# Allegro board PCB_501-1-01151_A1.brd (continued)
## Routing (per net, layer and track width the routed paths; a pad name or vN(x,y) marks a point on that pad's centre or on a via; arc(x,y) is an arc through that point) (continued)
VDD_PERI_3V3: length 139.9
  TOP w0.142: Q6.2 82.24,6.58 82.32,6.65 R261.1
  TOP w0.203: 29.21,41.15 29.21,41.14 U3.A1 ; U8.J10 77.97,25.64 v1(77.47,25.15) ; C38.1 v1(28.32,40.01) ; C38.1 v1(27.57,40) ; C38.1 v1(27.45,40.75) ; U8.F5 76.84,23.76 v1(76.84,24) 76.39,24 76.27,23.89 U8.E6 ; 29.08,40.26 U3.B1 U3.A1 ; U3.A1 29.23,40.76 29.08,40.62 29.08,40.39 ; U8.K9 78.98,25.91 v1(78.98,25.91)
  TOP w0.381: v1(36.98,26.45) 36.98,26.09 R812.2 ; R176.1 v1(22.46,39.75) ; R785.2 48.9,18.41 ; R177.1 v1(8.27,47.14) ; R267.2 R854.2 13.46,56.77 14.48,55.75 14.48,55.69 v1(14.53,55.64) ; v1(51.05,16.79) 50.97,16.87 C120.1 ; R264.1 v1(2.39,49.8) ; v1(12.7,51.04) 12.7,51.05 12.85,51.2 R857.2 R855.2 ; FB9.1 57.51,4.57 57.28,4.33 v1(57.28,3.58) ; v1(16.26,71.63) 14.85,70.22 D29.2 ; v1(37.34,15.75) 37.02,15.43 R811.2 36.57,16.04 36.6,16.06 R810.2 ; R813.2 36.94,27.88 v1(37.11,28.05) ; FB6.1 69.72,4.22 v1(69.31,3.8) ; v1(15.49,72.39) 15.11,72.01 R265.2 ; v1(20.55,49.66) C585.1 C586.1 H4.5 ; R116.1 v1(15.24,36.85) ; C190.1 64.33,17.04 64.41,17.12 v1(64.62,17.12) ; R262.1 v1(84.84,5.97) ; C597.1 v1(80.54,58.29) ; C597.1 v1(80.54,56.79) ; C597.1 v1(81.28,57.53) ; v1(42.04,18.8) FB1.1 v1(42.78,19.54) ; C114.1 94.6,19.85 C115.1 94.33,18.41 v1(93.5,19.24) ; v1(33.15,10.03) R109.1 R110.2 ; R261.1 82.92,7.37 82.94,7.35 C198.1 v1(84.56,7.35) ; R120.2 v1(21.61,36.85) ; R128.2 R124.1 v1(32.89,35.81) ; R113.2 v1(44.07,20.07)
  TOP w0.508: 52.04,16.76 C117.1 ; C117.1 53.18,16.76 ; C117.1 52.61,16.19
  L4_SIG2 w0.381: v1(28.96,47.63) 31.12,47.63 31.86,48.37 v1(31.86,50.27)
  BOTTOM w0.203: U10.78 51.21,16.95 v1(51.05,16.79)
  BOTTOM w0.254: C118.1 44.83,12.59 44.83,12.95 45.22,13.34 U10.11 ; U13.8 84.19,63.23 84.46,63.5 84.46,63.57 84.47,63.59 C128.1 v1(84.47,65.13) ; U10.51 45.72,28.27 45.59,28.39 C121.1 ; U10.65 53.2,23.45 53.3,23.35 C119.1
  BOTTOM w0.305: U20.3 18.84,46.04 v1(19.87,47.06) ; U23.4 32.17,70.57 31.98,70.76 C181.1
  BOTTOM w0.356: v1(8.13,44.7) 8.36,44.94 C170.1 C171.1 10.33,44.77 U20.12
  BOTTOM w0.381: R131.1 v1(16.62,12.34) ; R863.1 v1(40.51,9.62) ; R847.2 v1(38.33,33.29) ; R571.1 v1(50.16,10.54) ; R114.2 50.06,9.51 v1(50.15,9.42) ; v1(78.98,25.91) 79.1,25.8 C104.1 ; R180.2 R168.1 v1(11.28,41.89) ; C181.1 v1(31.12,71.5) 31.1,71.52 R185.2 ; v1(93.6,20.03) 93.85,19.77 94.15,19.77 ; v1(20.83,41.4) 20.96,41.27 C172.1 ; v1(10.68,38.83) 10.27,39.24 C173.1 ; U24.7 61.95,17.5 v1(62.23,17.78) ; v1(58.34,14) 58.67,14 C188.1 59.06,13.6 U24.1 ; v1(32.77,67.94) 33.01,67.7 U23.16 ; U22.16 v1(28.96,47.63) ; FB19.1 5.95,28.22 6.06,28.33 6.06,29.43 7.62,30.99 7.88,30.99 7.9,31.01 FB20.1 9.12,31.62 v1(9.65,31.62) ; J2.4 94.15,19.77 ; 94.15,19.77 93.84,19.46 93.72,19.46 v1(93.5,19.24) ; R845.2 38.1,10.11 v1(37.84,9.85) ; R799.2 v1(44.7,30.99) ; v1(18.03,51.1) 18.54,50.59 18.54,49.15 18.14,48.75 R167.2 ; C103.1 77.24,23.6 v1(76.84,24) ; FB18.1 v1(19.58,23.13) ; v1(85.86,95.89) D9.2 v1(86.74,95.12) ; R846.1 R864.1 41.27,33.81 v1(41.4,33.94) ; v1(54.1,13.08) 54.38,12.81 R130.2 ; R798.2 44.94,10.27 v1(45.13,10.08) ; R844.1 39.37,10.41 v1(39.62,10.16) ; R783.2 v1(53.59,10.54) ; C118.1 v1(44.81,11.83) ; R387.2 33.06,40.51 32.64,40.09 v1(32.64,39.37) ; v1(31.86,50.27) C180.1 31.86,48.92 31.84,48.9 U22.4 ; v1(64.62,17.12) 65.05,17.55 66.48,17.55 U24.10 ; R77.1 v1(79.88,18.13) ; v1(58.62,16.79) C607.1 58.35,16.05 58.22,15.91 Y1.4 ; C119.1 v1(53.85,22.61) ; R115.2 v1(50.93,32.38) ; C105.1 77.11,25.51 v1(77.47,25.15) ; FB17.1 v1(26.82,18.31) ; R134.1 v1(20.68,12.34) ; R784.2 v1(54.5,26.31) ; C121.1 v1(44.72,29.06)
  vias: v1(28.32,39.24) v1(33.58,31.56) v1(34.22,31.58) v1(34.89,31.59) v1(53.47,14.1) v1(54.23,14.1) v1(81.91,60.96) v1(82.04,59.18) v1(82.04,57.66)
VDD_PERI_FIL_3V3: length 29.1
  TOP w0.254: v1(75.82,73.66) 75.82,73.41 75.5,73.09 U14.64 ; v1(75.98,67.07) 75.81,67.07 75.78,67.09 U14.52 ; v1(72.52,74.55) 72.49,74.52 U14.5 ; v1(75.95,69.59) U14.57 ; U14.24 65.55,69.59 65.52,69.62 v1(65.52,69.62) ; U14.10 69.99,74.43 v1(70.1,74.55) ; U14.46 v1(73.49,64.18)
  TOP w0.381: R162.1 v1(80.42,64.39) ; R816.2 v1(64.9,62.74) ; R163.1 80.58,67.82 v1(80.81,67.59) ; R817.2 v1(61.72,67.47) ; R140.1 v1(72.64,58.01) ; R820.2 68.33,61.72 v1(68.07,61.47) ; R161.1 v1(80.42,65.53) ; R819.2 v1(60.8,72.77) ; R818.2 v1(60.93,70.49) ; R142.1 v1(70.1,58.01) ; R141.1 v1(73.79,58.01) ; R165.1 v1(80.42,66.68)
  BOTTOM w0.254: C142.1 v1(72.52,74.55) ; C139.1 v1(70.1,74.55)
  BOTTOM w0.305: C140.1 75.81,69.72 v1(75.95,69.59)
  BOTTOM w0.381: 66.04,72.14 66.27,71.9 C131.1 C133.1 66,70.1 v1(65.52,69.62) ; C143.1 C141.1 75.96,67.06 v1(75.98,67.07) ; v1(73.49,64.18) 73.53,64.22 C137.1 ; R143.1 67.33,76.09 ; C138.1 v1(75.82,73.66)
  BOTTOM w0.508: 68.33,76.66 R143.1 68.9,76.09 ; 74.11,64.88 C137.1 72.96,64.88 ; 70.68,73.81 C139.1 69.53,73.81 ; 75.33,68.77 C143.1 75.9,68.2
  vias: v1(75.73,59.47) v1(75.83,60.45) v1(76.84,60.45)
VDD_PMIC_LS_5V0: length 29
  TOP w0.178: R187.1 31.99,58.54 32.72,59.26 32.72,65.11 32.51,65.32 v1(32.51,65.79)
  TOP w0.203: U6.T12 57.51,47.67 57.51,47.9 U6.U12
  TOP w0.254: R187.1 31.99,56.38 v1(31.62,56.01) ; U6.U12 57.38,48.6
  TOP w0.508: 59.54,58.14 59.54,56.44 58.69,55.6 58.55,55.6 56.93,53.99 56.93,52.92 57.55,52.3 C94.1 C95.1 57.55,49.49 57.47,49.41 57.47,48.68 57.38,48.6
  BOTTOM w0.178: v1(32.51,65.79) 33.05,65.25 34.02,65.25 35.25,66.48 U23.14
  BOTTOM w0.381: R36.1 29.44,88.12
  vias: v1(31.62,55.24) v1(32.38,56.01) v1(32.38,55.24) v1(55.07,51.71) v1(59.05,59.18) v1(59.56,58.55) v1(59.82,59.18) v1(88.39,57.4) v1(88.77,58.42) v1(88.94,57.68) v1(88.9,56.77)
VDD_PMIC_LS_5V0_SNS: length 16.7
  TOP w0.178: v1(33.27,65.79) 33.27,65.32 33.1,65.14 33.1,59.49 33.79,58.79 R187.2 ; U1.33 40.47,57.93 39.95,57.4 39.22,57.4
  TOP w0.381: R187.2 v1(34.92,57.28)
  BOTTOM w0.178: U23.15 34.6,66.68 34.34,66.42 33.71,66.42 33.12,67.01 32.87,67.01 32.69,66.83 32.69,66.37 v1(33.27,65.79)
  vias: v1(35.69,57.28) v1(50.8,58.17) v1(51.44,58.17)
VDD_SNVS_CAP: length 13.7
  TOP w0.203: U6.N12 v1(57.38,45.4)
  L4_SIG2 w0.142: v1(57.38,45.4) 57.79,45.8 57.79,48.22 56.1,49.91 52.45,49.91 52.24,50.12 51.51,50.12 51.3,49.91 v1(51.05,49.91)
  BOTTOM w0.142: TP54.1 49.78,49.75 49.94,49.91 v1(51.05,49.91)
  BOTTOM w0.381: v1(57.38,45.4) 57.4,45.38 C62.1
VDD_SNVS_IN: length 92.5
  TOP w0.203: U6.P12 v1(57.38,46.2)
  TOP w0.381: v1(57.02,62.23) 56.85,62.06 U2.5 v1(57.79,61.36) ; v1(52.83,69.09) 52.83,68.73 R27.1 ; v1(37.19,66.68) R802.1 v1(36.54,67.69) ; v1(41.15,47.62) 41.29,47.48 R26.1 ; v1(55.92,67.94) 56.5,67.94 57.02,67.42 R23.1 ; R18.2 v1(55.63,64.87)
  TOP w0.508: v1(35.69,43.81) 35.94,44.07 35.94,45.08 D6.1 34.67,45.21 34.16,44.7 v1(34.16,43.43) ; TP36.1 36.7,68.45
  L4_SIG2 w0.381: v1(92.18,58.8) 90.4,60.58 83.48,60.58 82.51,61.56 74.26,61.56 73.53,60.83 66.68,60.83 65.95,61.56 63.79,61.56 62.48,62.87 58.55,62.87 57.79,62.1 v1(57.79,61.36)
  BOTTOM w0.142: v1(57.38,46.2) 57.62,46.2 58.02,46.6 60.06,46.6 60.2,46.74 60.2,47.49 60.61,47.9 C61.1
  BOTTOM w0.508: R32.2 16.91,76.71 v1(15.75,76.71) ; v1(92.18,58.8) 92.18,56.58 95.52,53.23 R576.1 R575.1 ; R763.2 37.97,65.89 v1(37.19,66.68)
  vias: v1(19.68,68.96) v1(20.7,68.96) v1(20.7,67.94) v1(35.14,43.43) v1(35.94,66.77)
VDD_SOC_ARM_IN: length 57.9
  TOP w0.142: U1.47 45.87,55.35 46.92,54.3 46.92,53.67 46.93,53.66 46.93,53.32 46.92,53.31 46.92,49.98 46.86,49.93 v1(46.86,49.53)
  TOP w0.254: U6.K10 v1(58.98,43) ; U6.J9 v1(60.61,41.37) ; U6.H9 v1(60.61,40.57) ; U6.H10 v1(58.98,40.57) ; U6.J10 v1(58.98,41.37) ; U6.K9 v1(60.61,43)
  BOTTOM w0.142: 60.96,43.43 61.01,43.48 61.01,45.18 60.99,45.2 60.99,45.65 60.84,45.8 56.42,45.8 56.19,46.03 56.19,46.36 55.95,46.6 55.38,46.6 54.58,47.4 52.55,47.4 52.32,47.62 50.04,47.62 48.76,48.9 47.15,48.9 47.09,48.96 47.09,48.97 46.86,49.19 v1(46.86,49.53) ; U22.11 30.54,43.1 31.1,42.55 45.34,42.55 45.88,43.09 45.88,47.13 47.35,48.61 48.64,48.61 48.99,48.26 48.99,47.28 49.28,46.99 v1(50.16,46.99)
  BOTTOM w0.381: v1(58.98,43) 59.66,43.67 C45.1 59.94,43.67 v1(60.61,43)
  vias: v1(50.8,46.99) v1(50.81,46.24) v1(51.69,46.99) v1(51.69,46.23)
VDD_SOC_ARM_IN_SNS: length 27
  BOTTOM w0.142: v1(47.75,47.75) 47.75,47.5 48.01,47.24 48.5,47.24 48.64,47.39 48.64,48.12 48.5,48.26 47.5,48.26 46.23,46.99 46.23,42.95 45.48,42.2 30.95,42.2 29.89,43.27 U22.12
VDD_SOC_CAP: length 23.1
  TOP w0.203: U6.J11 v1(58.18,41.37) ; U6.H8 v1(61.41,40.57) ; U6.L11 58.2,43.78 v1(58.16,43.78) ; U6.K11 v1(59.01,42.17) ; U6.L9 v1(60.61,43.8) ; U6.L8 v1(61.41,43.8) ; U6.L10 v1(58.98,43.8) ; U6.G8 v1(61.41,39.77) ; U6.K8 v1(61.41,43)
  TOP w0.254: U6.H8 61.09,41.07 61.09,41.69 U6.J8 U6.K8
  BOTTOM w0.142: 66.42,44.42 65.8,44.42 65.58,44.2 65.25,44.2 65.01,44.43 65.01,44.84 64.86,45 61.7,45
  BOTTOM w0.203: 61.7,45 61.41,44.71 v1(61.41,43.8)
  BOTTOM w0.381: v1(61.41,43.8) v1(61.41,43) 61.32,42.91 C51.1 61.32,40.98 61.34,40.97 C52.1 61.34,40.9 61.34,40.89 61.34,40.73 61.41,40.66 v1(61.41,40.57) v1(61.41,39.77) ; 66.42,44.42 66.9,44.42 67.06,44.58 67.06,45.22 67.91,46.08 ; TP50.1 68.07,45.09 67.91,45.25 67.91,46.08 ; 67.91,46.08 C54.1 ; v1(58.16,43.78) 58.17,43.8 C53.1 v1(58.98,43.8)
VDD_USB_VBUS1: length 5.1
  BOTTOM w0.508: U18.15 93.6,67.48 C149.1 93.69,68.52 93.71,68.54 C150.1 93.71,69.68 FB10.1
VDD_USB_VBUS2: length 4.9
  BOTTOM w0.508: U18.14 92.33,66.97 C151.1 91.73,69.07 C152.1 FB11.1
VDD_USB_VBUS3: length 6.4
  BOTTOM w0.508: U18.11 88.52,68.01 88.68,68.17 C153.1 88.68,70.59 C154.1 88.67,71.84 FB12.1
VDD_USB_VBUS4: length 6.8
  BOTTOM w0.508: U18.10 87.25,67.22 85.47,69 C155.1 83.71,69 C156.1 FB13.1
VDD_USB_VBUS5: length 5.2
  BOTTOM w0.381: U19.8 49.85,74.29 C166.1 48.66,74.36 48.62,74.4 C167.2 FB14.1
VIN_PMIC_5V0: length 77.4
  TOP w0.142: v1(41.3,56.22) 41.3,56.3 41.09,56.51 U1.36
  TOP w0.203: 31.75,83.44 U5.B2 U5.A2 ; 31.75,83.44 31.5,83.44 ; 31.75,83.44 31.5,83.19 ; U5.A2 31.88,82.55 31.88,82.55 ; U5.A2 31.5,82.94 31.5,82.93
  TOP w0.254: P1.2 20.19,81.03 ; C5.1 v1(30.1,77.47)
  TOP w0.381: v1(26.86,55.28) 26.54,55.59 DA8.1 ; H4.1 20.17,50.29 C584.1 20.55,51.33 20.54,51.35 C583.1 ; C583.1 v1(19.67,52.2) ; C583.1 v1(20.54,53.38) ; R7.2 28.32,82.3 ; R781.1 v1(22.48,53.98) ; H4.3 19.31,49.02 v1(19.89,49.6) ; R10.2 v1(53.83,62.5) ; R20.2 v1(92.84,71.12)
  L4_SIG2 w0.381: v1(92.84,71.12) 92.24,70.52 92.24,65.13 88.28,61.16 85.73,61.16 84.41,62.48 68.83,62.48 68.45,62.1 66.21,62.1 65.49,62.82 65.49,62.99 65.03,63.45 57.4,63.45 55.92,61.98 54.36,61.98 v1(53.83,62.5)
  BOTTOM w0.381: v1(19.89,49.6) 19.89,51.98 v1(19.67,52.2) ; v1(48.64,61.47) 50.04,62.87 50.29,62.87 50.33,62.91 53.42,62.91 v1(53.83,62.5) ; v1(38.71,65.28) 38.73,65.26 38.73,65.02 39.22,64.54 R12.2 ; R22.2 46.74,62.61 47.12,62.23 ; 40.13,55.95 v1(40.13,55.37)
  vias: v1(26.03,81.15) v1(26.8,80.14) v1(26.8,78.87) v1(26.8,77.6) v1(27.69,81.15) v1(28.58,80.14) v1(28.58,78.87) v1(28.58,77.72) v1(30.1,80.14) v1(30.1,78.87) v1(38.79,58.96) v1(38.8,58.34) v1(39.9,58.26) v1(41.2,55.62) v1(44.45,54.86) v1(44.83,54.36) v1(47.06,56.23) v1(47.69,56.22) v1(47.89,61.47) v1(48.7,58.67) v1(49.31,58.67)
BASE_CC#: length 39.1
  TOP w0.142: Q17.1 21.9,56.07 22.22,56.39 v1(27.3,56.39)
  BOTTOM w0.142: v1(27.3,56.39) 29.84,53.85 33.15,53.85 33.91,54.61 33.91,58.29 35.84,60.23 35.84,65.18 36.58,65.91 36.58,66.81 37.08,67.31 41.15,67.31 42.67,65.79 R766.2
BOOST0: length 5.2
  TOP w0.142: U14.50 75.68,66.09 76.2,65.57 76.2,65.26 78.21,63.25 R149.1
BOOST1: length 1.7
  TOP w0.142: R152.1 74.55,63.76 74.49,63.81 U14.48
BOOT_MODE0: length 54.5
  TOP w0.142: v1(60.42,57.14) 60.2,56.92 60.2,56.29 58.42,54.51 58.42,53.59 58.42,49.05 58.75,48.71 58.86,48.71 58.99,48.58 58.99,47.79 U6.T10
  BOTTOM w0.142: SW7.2 93.22,47.88 87,54.1 69.59,54.1 66.8,56.9 60.66,56.9 v1(60.42,57.14)
BOOT_MODE1: length 51
  TOP w0.142: U6.U10 59.4,48.56 58.77,49.19 58.77,52.09 58.77,54.32 60.51,56.07 60.77,56.07 v1(61.09,56.39)
  BOTTOM w0.142: SW7.1 91.95,48.26 86.49,53.72 69.48,53.72 66.82,56.39 v1(61.09,56.39)
BUSY: length 8.6
  BOTTOM w0.142: R199.2 62.16,20.03 62.37,20.03 64.1,18.3 64.1,16.1 64.65,15.55 U24.13
CCM_PMIC_STBY_REQ: length 79.9
  TOP w0.142: U6.U9 60.2,48.79 59.6,49.39 59.6,52.03 61.98,54.41 61.98,58.56 60.42,60.11 60.42,62.64 58.67,64.39 58.67,70.48 58.66,70.49 v1(58.66,70.94)
  L3_SIG1 w0.142: v1(30.73,78.1) 32,79.38 37.72,79.38 38.73,78.36 47.3,78.36 51.44,74.23 55.83,74.23 58.66,71.4 v1(58.66,70.94)
  BOTTOM w0.142: R765.1 34.18,60.05 33.66,60.58 33.66,63.25 27.91,68.99 27.91,74.17 30.73,76.99 v1(30.73,78.1)
CLOCK_50MHZ: length 2.5
  BOTTOM w0.142: R132.1 56.84,19.63 Y1.3
CMD: length 15.5
  TOP w0.076: 78.44,20.96 78.72,21.24 78.72,22.49 78.51,22.71 78.51,23.09 78.85,23.43 79.18,23.43 79.22,23.39 U8.M5
  TOP w0.142: 78.44,20.96 77.16,19.68 70.16,19.68 68.47,18 R830.2
COLL_CC#: length 4.8
  TOP w0.254: DA8.2 24.22,55.59 24.17,55.65 R782.1 R781.2 21.93,55.65 21.41,55.12 Q17.3
CRS_DV_A: length 3.8
  BOTTOM w0.142: U10.1 50.22,13.23 50.62,12.83 51.06,12.83 51.31,12.57 R572.1 R119.2
CRS_DV_B: length 5.9
  BOTTOM w0.142: R126.2 R574.1 52.07,28.07 52.96,27.18 52.96,25.84 52.57,25.45 U10.61
CS#: length 9
  BOTTOM w0.142: U24.15 65.03,14.25 63.99,15.29 63.99,15.72 63.75,15.96 63.75,18.16 62.23,19.68 R201.2
CSENS2_A0: length 2.7
  BOTTOM w0.142: U23.5 33.95,71.81 33.25,72.52 R185.1
DAT0: length 7.1
  TOP w0.076: 72.9,22.03 73.08,22.03 73.43,22.39 73.66,22.39 U8.A3
  TOP w0.142: 72.9,22.03 72.84,22.03 72.53,21.72 71.93,21.72 71.81,21.84 71.81,21.88 71.68,22.01 71.5,22.01 71.38,21.88 71.38,21.84 71.25,21.72 71.08,21.72 70.95,21.84 70.95,21.88 70.83,22.01 70.65,22.01 70.53,21.88 70.53,21.84 70.4,21.72 70.22,21.72 70.1,21.84 70.1,22.11 69.97,22.23 69.8,22.23 69.67,22.11 69.67,21.84 69.55,21.72 R822.2
DAT1: length 10.4
  TOP w0.142: R823.2 68.98,24 69.11,24.13 69.11,24.58 69.23,24.71 69.41,24.71 69.53,24.58 69.53,24.13 69.66,24 69.98,24 70.14,23.84 70.14,23.3 70.56,22.88 70.93,22.88 71.06,23 71.06,23.98 71.18,24.1 71.46,24.1 71.58,23.98 71.58,23.79 71.7,23.68 71.99,23.68 72.09,23.58 72.09,23.38 71.99,23.27 71.68,23.27 71.58,23.18 71.58,23 71.71,22.88 73.08,22.88 73.23,23.04 73.54,23.04 73.69,22.89 U8.A4
DAT2: length 7.5
  TOP w0.076: 73.55,23.39 U8.A5 ; 72.9,23.39 73.16,23.39
  TOP w0.142: 73.16,23.39 73.55,23.39 ; R824.2 68.83,25.15 69.02,25.33 69.02,25.72 69.16,25.86 69.4,25.86 69.58,25.69 69.58,25.27 70.27,24.57 72.05,24.57 72.19,24.43 72.19,24.09 72.89,23.39 72.9,23.39
DAT3: length 9.1
  TOP w0.076: 74.21,21.21 74.21,21.63 U8.B2
  TOP w0.142: 74.21,21.21 74.21,20.38 73.94,20.11 73.64,20.11 73.52,20.23 73.52,20.79 73.39,20.91 73.21,20.91 73.09,20.79 73.09,20.23 72.96,20.11 69.15,20.11 R825.2
DAT4: length 10.3
  TOP w0.076: 73.4,21.96 73.57,22.13 74.21,22.13 U8.B3
  TOP w0.142: 73.4,21.96 72.62,21.17 72.62,20.69 72.51,20.57 72.08,20.57 71.95,20.7 71.95,21.16 71.83,21.29 71.65,21.29 71.52,21.16 71.52,20.7 71.4,20.57 71.22,20.57 71.1,20.7 71.1,21.12 70.97,21.25 70.8,21.25 70.67,21.12 70.67,20.7 70.55,20.57 70.37,20.57 70.24,20.7 70.24,21.12 70.12,21.25 69.94,21.25 69.82,21.12 69.82,20.7 69.69,20.57 R826.2
DAT5: length 7.5
  TOP w0.076: 73.48,22.65 74.22,22.65 U8.B4
  TOP w0.142: R827.2 68.93,22.86 69.11,23.04 69.11,23.49 69.21,23.59 69.43,23.59 69.56,23.46 69.56,22.98 69.68,22.86 69.98,22.86 70.38,22.45 73.08,22.45 73.27,22.65 73.48,22.65
DAT6: length 7.5
  TOP w0.076: U8.B5 74.22,23.63 73.71,23.63
  TOP w0.142: R828.2 69.58,26.29 70.67,25.2 72.24,25.2 72.69,24.75 72.69,24.24 73.13,23.79 73.46,23.79 73.62,23.63 73.71,23.63
DAT7: length 10
  TOP w0.076: 73.6,25.31 73.77,25.15 74.07,25.15 74.22,24.99 74.22,24.13 U8.B6
  TOP w0.142: 73.6,25.31 73.16,25.76 73.11,25.76 72.99,25.88 72.99,26.14 72.86,26.27 72.69,26.27 72.56,26.14 72.56,25.88 72.44,25.76 72.26,25.76 72.13,25.88 72.13,26.14 72.01,26.27 71.83,26.27 71.71,26.14 71.71,25.88 71.58,25.76 71.14,25.76 70.79,26.11 70.61,26.11 70.61,26.1 70.43,26.1 70.31,26.23 70.31,26.41 70.35,26.46 70.35,26.63 70.23,26.76 70.05,26.76 70,26.71 69.83,26.71 69.7,26.83 69.7,27.01 69.71,27.02 69.71,27.19 69.47,27.43 R829.2
DC34_SEL: length 4.4
  TOP w0.142: v1(44.41,63.42) 44.69,63.13 44.69,62.54 44.67,62.51 U1.17
  BOTTOM w0.142: R21.1 44.34,64.39 44.34,63.48 v1(44.41,63.42)
DC_SW: length 3.6
  TOP w0.203: R5.1 15.48,93.75 15.49,93.76 SW1.1
DC_SW_CTL: length 27.9
  TOP w0.203: D2.1 25.79,84.99 25.98,84.79 27.77,84.79 28.07,85.09 28.07,92.2 27.57,92.69 R5.2
  TOP w0.381: D2.1 C2.2 R3.1 24.66,83.08 24.14,82.56 Q1.3
DDR_ZQPAD: length 4.4
  TOP w0.142: R63.2 87.07,37.63 84.18,37.63 U7.L8
DEBUG_5V0: length 14.1
  TOP w0.381: v1(9.81,43.68) 9.68,43.56 C174.1 8.91,43.54 FB4.2
  BOTTOM w0.381: R175.1 10.57,49.55 10.55,49.53 8.89,49.53 6.73,47.37 6.73,44.2 7.24,43.68 v1(9.81,43.68)
DEBUG_DN: length 1.8
  TOP w0.127: U21.B1 9.04,40.51 9.11,40.45 9.82,40.45 R172.1
DEBUG_DP: length 1.8
  TOP w0.127: U21.A1 9.04,40.11 9.11,40.18 9.84,40.18 R171.1
DEBUG_RESET#: length 5.6
  BOTTOM w0.142: R831.2 R180.1 9.27,43.06 9.41,43.21 10.31,43.21 10.76,43.65 10.91,43.65 11.39,44.13 U20.11
DEBUG_RXD: length 5.1
  BOTTOM w0.142: R170.1 15.11,48.26 15.52,47.85 15.52,46.07 16.19,45.4 U20.4
DEBUG_TXD: length 2.4
  BOTTOM w0.142: U20.1 16.74,47.31 16.4,47.64 16.4,47.65 16.26,47.79 R169.1
DEBUG_UART_RESET#: length 82.9
  TOP w0.142: U6.E5 v1(63.81,38.17)
  L4_SIG2 w0.142: v1(63.81,38.17) 63.62,38.17 63.21,37.77 62.85,37.77 62.61,37.54 62.61,36.4 62.7,36.31 62.7,33.54 60.63,31.47 60.63,28.22 60.25,27.84 57.44,27.84 56.43,26.83 53.24,26.83 52.78,27.29 42.03,27.29 40.82,28.5 40.82,35.14 v1(41.15,35.46)
  BOTTOM w0.142: v1(41.15,35.46) 38.26,35.46 36.92,34.13 35.29,34.13 33.61,32.45 32.85,32.45 32.4,32 28.17,32 21.82,38.35 17.53,38.35 17.4,38.48 13.69,38.48 11.93,36.72 9.6,36.72 7.49,38.83 R831.1
DEBUG_USB_DN: length 3.1
  TOP w0.127: U21.B2 7.97,40.51 7.91,40.45 7.71,40.45 7.51,40.65 6.51,40.65 6.25,40.91 J8.2
DEBUG_USB_DP: length 3
  TOP w0.127: U21.A2 7.98,40.11 7.91,40.18 7.6,40.18 7.4,40.39 6.48,40.39 6.35,40.26 J8.3
DRAM_ADDR0: length 34.7
  TOP w0.142: U7.N3 v1(79.41,36.01) ; U6.L5 v1(63.81,43.8)
  L3_SIG1 w0.142: v1(79.41,36.01) 80.19,35.22 80.58,35.22 81.36,36 81.6,36 81.73,36.12 81.73,36.58 81.85,36.7 82.03,36.7 82.16,36.58 82.16,36.12 82.28,36 82.84,36 82.97,36.13 82.97,36.82 82.73,37.07 82.26,37.07 82.03,37.29 81.86,37.29 81.73,37.16 81.55,37.16 81.43,37.29 81.43,37.46 81.55,37.59 81.55,37.77 81.43,37.89 81.25,37.89 81.14,37.78 80.96,37.78 80.84,37.91 80.84,38.08 80.95,38.19 80.95,38.37 80.75,38.57 80.31,38.57 80.13,38.4 80.13,38.08 80.94,37.27 80.94,36.95 80.8,36.81 80.33,36.81 79.92,36.41 79.24,36.41 79.01,36.64 79.01,37.05 78.86,37.2 78.77,37.2 78.77,37.2 76.92,37.2 74.9,39.23 73.9,39.23 71.64,41.49 71.25,41.49 71.02,41.72 68.99,41.72 68.17,42.54 65.15,42.54 65.01,42.68 65.01,43.16 64.78,43.4 64.21,43.4 v1(63.81,43.8)
DRAM_ADDR1: length 34.7
  TOP w0.142: v1(69.47,40.26) 67.31,40.26 67.04,40.53 66.25,40.53 U6.H2 ; U7.P7 v1(83.41,35.21)
  BOTTOM w0.142: v1(83.41,35.21) 83.81,35.61 86.06,35.61 86.25,35.79 86.25,36.24 86.08,36.41 83.24,36.41 83.21,36.43 82.81,36.43 82.59,36.66 82.59,37.52 81.95,38.16 80.45,38.16 79.81,38.8 78.16,38.8 77.6,39.37 76.71,39.37 74.98,41.1 74.98,42.48 74.53,42.93 72.94,42.93 72.74,43.13 72.74,43.92 71.95,44.71 71.08,44.71 70.24,43.87 70.24,43.23 70.87,42.61 70.87,41.99 70.62,41.75 69.73,41.75 69.47,41.49 v1(69.47,40.26)
DRAM_ADDR2: length 34.8
  TOP w0.142: U7.P3 v1(79.41,35.21) ; U6.K1 66.97,42.58 66.98,42.59 67.46,42.59 67.6,42.73 67.95,42.73 67.98,42.77 68.92,42.77 69.02,42.87 70.52,42.87 71.85,41.53 71.85,39.87 71.63,39.65 71.63,39.61 71.63,39.61 v1(71.63,37.85)
  BOTTOM w0.142: v1(79.41,35.21) 79.73,35.52 79.73,35.64 80.28,36.18 80.76,36.18 80.95,36 80.95,34.11 81.1,33.96 81.34,33.96 81.47,34.09 81.47,35.46 81.59,35.58 82.21,35.58 82.4,35.4 82.4,34.17 82.54,34.03 82.77,34.03 82.91,34.17 82.91,35.76 82.77,35.9 81.58,35.9 80.96,36.51 79.77,36.51 79.66,36.41 78.41,36.41 78.21,36.2 78.21,35.77 78.04,35.6 77.46,35.6 77.32,35.47 75.41,35.47 74.63,36.24 71.95,36.24 71.63,36.56 v1(71.63,37.85)
DRAM_ADDR3: length 35.2
  TOP w0.142: U6.M2 66.2,43.78 67.53,43.78 67.68,43.93 70.91,43.93 72.94,41.91 72.94,38.52 73.06,38.39 73.06,38.38 73.13,38.31 v1(73.13,37.65) ; U7.N2 v1(78.61,36.01)
  L3_SIG1 w0.142: v1(78.61,36.01) 78.66,36.06 78.87,36.06 79,35.92 79,35.72 78.89,35.61 77.32,35.61 77.19,35.73 77.19,35.89 77.07,36.02 76.89,36.02 76.77,35.89 76.77,35.73 76.64,35.61 76.46,35.61 76.34,35.73 76.34,35.89 76.21,36.02 76.04,36.02 75.91,35.89 75.91,35.73 75.79,35.61 75.49,35.61 74.89,36.21 72.55,36.21 72.17,36.59 68.96,36.59 68.04,37.51 67.48,37.51 67.22,37.77 67.22,38.09 67.36,38.23 68.34,38.23 68.53,38.42 68.53,38.78 68.65,38.91 68.83,38.91 68.96,38.78 68.96,38.46 69.08,38.33 71.85,38.33 72.13,38.06 72.13,37.86 72.28,37.7 72.89,37.7 72.94,37.65 v1(73.13,37.65)
DRAM_ADDR4: length 35.3
  TOP w0.142: U6.K4 v1(64.61,43) ; U7.P8 v1(84.21,35.21)
  L3_SIG1 w0.142: v1(64.61,43) 64.03,42.42 63.12,42.42 62.61,41.91 62.61,36.11 64.95,33.78 67.17,33.78 70.45,30.5 79.5,30.5 v1(84.21,35.21)
DRAM_ADDR5: length 35.1
  TOP w0.142: U6.L1 66.97,43.38 67.03,43.43 67.67,43.43 67.83,43.59 70.77,43.59 72.57,41.79 72.57,38.25 72.6,38.22 v1(72.6,38.18) ; U7.P2 v1(78.61,35.21)
  L3_SIG1 w0.142: v1(72.6,38.18) 71.96,38.82 70.46,38.82 70,39.27 69.66,39.27 69.45,39.49 68.99,39.49 68.78,39.27 68.1,39.27 67.98,39.15 67.98,38.73 67.85,38.6 67.68,38.6 67.55,38.73 67.55,39.15 67.43,39.27 66.96,39.27 66.76,39.07 66.76,37.84 67.43,37.18 67.83,37.18 68.69,36.32 69.47,36.32 69.66,36.13 71.98,36.13 72.94,35.17 73.49,35.17 73.62,35.29 73.62,35.69 73.74,35.82 73.92,35.82 74.04,35.69 74.04,35.29 74.17,35.17 74.34,35.17 74.47,35.29 74.47,35.69 74.59,35.82 74.77,35.82 74.9,35.69 74.9,35.29 75.02,35.17 76.5,35.17 76.86,34.8 77.98,34.8 78.39,35.21 v1(78.61,35.21)
DRAM_ADDR6: length 34.9
  TOP w0.142: U6.G2 66.25,39.73 67.07,39.73 67.24,39.57 68.91,39.57 69.1,39.38 69.88,39.38 70.46,38.8 70.46,37.36 73.01,34.81 73.19,34.81 73.74,35.37 73.92,35.37 74.05,35.24 74.05,35.07 73.49,34.51 73.49,34.33 73.61,34.21 73.79,34.21 74.35,34.77 74.52,34.77 74.65,34.64 74.65,34.47 74.09,33.91 74.09,33.73 74.22,33.6 74.39,33.6 74.95,34.16 75.13,34.16 75.25,34.04 75.25,33.86 74.69,33.3 74.69,33.13 74.92,32.9 75.1,32.9 75.45,33.25 75.63,33.25 75.75,33.13 75.75,32.95 75.36,32.56 75.14,32.56 75.02,32.44 75.02,32.16 75.16,32.01 82.19,32.01 82.32,32.14 82.32,32.57 82.44,32.7 82.62,32.7 82.74,32.57 82.74,32.14 82.87,32.01 83.07,32.01 83.21,32.15 83.21,32.58 83.31,32.68 83.56,32.68 83.67,32.58 83.67,32.34 83.79,32.21 83.99,32.21 84.58,32.79 84.58,33.25 84.2,33.62 84.2,34.41 U7.R8
DRAM_ADDR7: length 34.9
  TOP w0.142: U6.H4 v1(64.61,40.57) ; U7.R2 v1(78.61,34.41)
  L3_SIG1 w0.142: v1(78.61,34.41) 78.61,34.26 78.21,33.86 78.21,33.38 77.97,33.15 77.07,33.15 76.94,33.27 76.94,33.54 76.82,33.67 76.64,33.67 76.51,33.54 76.51,33.27 76.39,33.15 75.98,33.15 75.86,33.27 75.86,34.17 75.73,34.3 75.55,34.3 75.43,34.17 75.43,33.27 75.3,33.15 75.13,33.15 75,33.27 75,34.17 74.88,34.3 74.7,34.3 74.57,34.17 74.57,33.27 74.45,33.15 74.27,33.15 74.15,33.27 74.15,34.17 74.02,34.3 73.85,34.3 73.72,34.17 73.72,33.27 73.6,33.15 73.42,33.15 73.29,33.27 73.29,34.17 73.17,34.3 72.99,34.3 72.87,34.17 72.87,33.27 72.74,33.15 72.45,33.15 72.32,33.28 72.32,33.6 72.2,33.71 71.84,33.71 71.71,33.84 71.71,35.18 71.59,35.3 71.41,35.3 71.29,35.18 71.29,33.84 71.16,33.71 70.41,33.71 70.18,33.94 70.18,34.11 70.58,34.51 70.58,34.69 70.45,34.81 70.28,34.81 69.88,34.42 69.71,34.42 69.58,34.54 69.58,34.72 69.98,35.11 69.98,35.29 69.85,35.41 69.67,35.41 69.28,35.02 69.1,35.02 67.51,36.61 66.91,36.61 66.03,37.5 66.03,39.72 65.58,40.17 65.01,40.17 v1(64.61,40.57)
DRAM_ADDR8: length 34.8
  TOP w0.142: U7.T8 83.4,34.42 81.97,34.42 81.53,33.98 v1(81.53,33.53) ; v1(64.61,42.2) U6.J4
  L3_SIG1 w0.142: v1(64.61,42.2) 64.56,42.15 63.74,42.15 63.41,41.82 63.41,35.96 63.64,35.73 63.82,35.73 64.2,36.12 64.38,36.12 64.5,35.99 64.5,35.81 64.12,35.43 64.12,35.25 64.24,35.13 64.42,35.13 64.8,35.51 64.98,35.51 65.11,35.39 65.11,35.21 64.72,34.83 64.72,34.65 65.26,34.12 67.45,34.12 69.98,31.58 71.41,31.58 72.09,30.91 78.91,30.91 v1(81.53,33.53)
DRAM_ADDR9: length 34.8
  TOP w0.142: U6.L2 66.25,42.93 67.32,42.93 67.47,43.09 67.81,43.09 67.84,43.11 68.77,43.11 68.87,43.21 70.66,43.21 72.2,41.67 72.2,39.65 72.01,39.46 72.01,38.14 72.11,38.04 72.11,37.91 73.15,36.87 74.01,36.87 74.31,37.17 74.31,37.69 75.34,38.73 75.34,39.28 75.46,39.41 75.9,39.41 76.03,39.53 76.03,39.71 75.9,39.83 75.47,39.83 75.35,39.96 75.35,40.42 75.49,40.56 76.37,40.56 76.54,40.39 76.54,38.63 76.3,38.4 75.78,38.4 75.02,37.64 75.02,37.21 75.17,37.07 76.16,37.07 77.27,35.96 77.27,33.38 77.51,33.15 79.76,33.15 80.58,33.97 80.58,34.63 80.4,34.81 U7.R3
DRAM_ADDR10: length 34.7
  TOP w0.142: U6.M4 v1(64.61,44.6) ; U7.L7 v1(83.4,38.4)
  L3_SIG1 w0.142: v1(64.61,44.6) 64.79,44.6 65.19,45 67.32,45 67.32,44.99 68.85,44.99 69.47,44.38 70.59,44.38 71.62,43.34 72.38,43.34 73.72,42.01 74.31,42.01 76.62,39.7 81.19,39.7 81.73,40.24 82.39,40.24 82.7,39.93 84.07,39.93 84.61,40.47 84.61,41.77 84.84,42 85.47,42 85.66,42.19 85.66,42.55 85.99,42.88 86.68,42.88 87,42.56 87,42.11 84.88,39.99 84.88,39.05 84.64,38.8 83.81,38.8 v1(83.4,38.4)
DRAM_ADDR11: length 34.9
  TOP w0.142: v1(81.91,35.05) 82.16,34.81 U7.R7 ; U6.K3 v1(65.41,43)
  L3_SIG1 w0.142: v1(65.41,43) 69.65,43 v1(70.36,42.29)
  BOTTOM w0.142: v1(81.91,35.05) 81.91,33.97 82.25,33.63 83.78,33.63 83.92,33.49 83.92,33.21 83.78,33.06 77.17,33.06 74.41,35.82 71.03,35.82 70.17,36.68 69.13,36.68 68.65,37.17 68.65,42.33 69.07,42.76 69.89,42.76 v1(70.36,42.29)
DRAM_ADDR12: length 34.7
  TOP w0.142: U7.N7 82.29,37.12 82.29,37.54 82.6,37.85 82.6,38.07 82.5,38.18 82.06,38.18 81.5,38.74 81.5,39.45 82.58,40.54 82.58,41.63 81.3,42.91 81.09,42.91 80.95,42.77 80.95,42.56 81.88,41.64 81.88,40.23 81.04,39.39 81.04,38.6 80.51,38.07 80.51,37.33 v1(80.39,37.21) ; U6.L4 v1(64.61,43.8)
  L3_SIG1 w0.142: v1(80.39,37.21) 79.58,37.21 79.57,37.21 79.24,37.21 78.86,37.59 77.91,37.59 77.32,38.18 76.43,38.18 74.96,39.65 73.97,39.65 71.69,41.94 71.35,41.94 69.94,43.34 68.8,43.34 68.75,43.4 65.16,43.4 64.76,43.8 v1(64.61,43.8)
DRAM_ADDR13: length 34.8
  TOP w0.142: U6.H3 v1(65.41,40.57) ; U7.T3 v1(79.41,33.61)
  L3_SIG1 w0.142: v1(79.41,33.61) 80.31,34.51 82.42,34.51 82.56,34.37 82.56,34.17 82.42,34.02 81.38,34.02 81,33.65 80.82,33.65 80.7,33.76 80.52,33.76 80.38,33.63 80.38,33.45 80.5,33.33 80.5,33.14 80.37,33.01 80.18,33.01 80.07,33.13 79.88,33.13 79.75,33 79.75,32.81 79.87,32.7 79.87,32.51 79.74,32.38 79.55,32.38 79.44,32.5 79.25,32.5 79.12,32.37 79.12,32.18 79.24,32.06 79.24,31.88 78.61,31.25 74.57,31.25 74.36,31.47 74.13,31.47 73.91,31.25 73.68,31.25 73.47,31.47 73.23,31.47 73.02,31.25 72.23,31.25 71.55,31.93 70.15,31.93 67.55,34.53 65.8,34.53 65.47,34.86 65.47,35.45 65.01,35.91 65.01,36.74 64.78,36.97 64.45,36.97 64.21,37.2 64.21,40.73 64.45,40.97 64.5,41.02 64.96,41.02 v1(65.41,40.57)
DRAM_ADDR14: length 34.7
  TOP w0.142: U7.T7 82.26,34.01 82.16,33.9 82.16,33.55 82.28,33.43 83.78,33.43 83.92,33.29 83.92,33.12 83.81,33.01 82.12,33.01 81.53,32.42 81.38,32.42 81.25,32.55 81.25,32.82 81.13,32.95 80.95,32.95 80.83,32.82 80.83,32.55 80.7,32.42 76.34,32.42 76.1,32.66 76.1,33.54 76.24,33.68 76.43,33.68 76.57,33.83 76.57,34.03 76.43,34.17 75.96,34.17 75.81,34.31 75.81,34.51 75.96,34.65 76.42,34.65 76.56,34.8 76.56,35.36 76.56,35.54 76.44,35.66 76.26,35.66 75.39,34.79 75.17,34.79 75.04,34.92 75.04,35.11 75.81,35.88 75.81,36.05 75.69,36.18 75.51,36.18 74.73,35.4 74.45,35.4 74.27,35.58 74.27,36 74.1,36.17 73.51,36.17 73.34,36.01 73.34,35.6 73.19,35.45 72.86,35.45 72.67,35.64 72.67,35.82 72.8,35.96 72.8,36.13 72.68,36.26 72.47,36.26 72.35,36.14 72.17,36.14 72.05,36.26 72.05,36.44 72.15,36.54 72.15,36.72 72.03,36.85 71.85,36.85 71.75,36.74 71.57,36.74 70.81,37.5 70.81,39.05 70.13,39.73 69.24,39.73 69.05,39.91 67.27,39.91 67,40.18 U6.G1
DRAM_ADDR15: length 34.9
  TOP w0.142: U6.K5 v1(63.81,43) ; U7.M7 v1(83.41,36.81)
  L3_SIG1 w0.142: v1(83.41,36.81) 83.81,36.41 86.35,36.41 86.7,36.75 86.7,37.28 86.48,37.49 86.09,37.49 85.96,37.62 85.96,38.06 85.84,38.19 85.66,38.19 85.54,38.06 85.54,37.62 85.41,37.49 82.4,37.49 80.97,38.92 79.95,38.92 79.81,38.78 79.81,38.24 79.57,38.01 78.38,38.01 77.38,39.01 77.05,39.01 77.03,38.98 76.24,38.98 74.03,41.19 73.25,41.19 72,42.44 71.35,42.44 70.11,43.69 69.02,43.69 68.51,44.2 63.63,44.2 63.41,43.98 63.41,43.52 63.81,43.12 v1(63.81,43)
DRAM_CAS#: length 34.7
  TOP w0.142: v1(70.43,40.62) 70.43,40.74 69.77,41.4 68.96,41.4 68.65,41.09 67.6,41.09 67.31,41.38 66.2,41.38 U6.J2 ; U7.K3 79.55,38.81 79.41,38.66 v1(79.41,38.41)
  BOTTOM w0.142: v1(70.43,40.62) 69.93,40.62 69.79,40.76 69.79,41.21 69.92,41.34 70.82,41.34 71.3,41.83 71.3,42.7 70.73,43.27 70.73,43.87 71.13,44.27 71.89,44.27 72.34,43.82 72.34,43.49 72.2,43.35 72,43.35 71.57,43.78 71.3,43.78 71.17,43.65 71.17,43.39 71.69,42.87 71.69,41.42 71.84,41.28 72.04,41.28 72.18,41.42 72.18,42.65 72.32,42.79 72.52,42.79 72.64,42.67 72.64,41.38 72.77,41.25 72.95,41.25 73.08,41.37 73.08,42.44 73.22,42.58 73.42,42.58 73.58,42.42 73.58,41.33 73.69,41.22 73.88,41.22 73.99,41.33 73.99,42.44 74.13,42.58 74.36,42.58 74.63,42.31 74.63,40.94 76.57,39.01 77.4,39.01 77.72,38.68 77.72,38.35 78.07,38.01 79.01,38.01 v1(79.41,38.41)
DRAM_CS0#: length 34.7
  TOP w0.142: U7.L2 78.61,37.61 77.92,37.61 77.16,36.84 76.87,36.84 76.53,37.18 76.53,37.39 76.75,37.61 v1(77.22,37.61) ; v1(73.89,38.72) 73.89,39.17 73.67,39.39 73.67,42.16 71.2,44.62 66.16,44.62 U6.N2
  BOTTOM w0.142: v1(73.89,38.72) 73.48,39.13 70.18,39.13 69.91,39.39 69.91,39.92 70.05,40.05 70.64,40.05 70.79,39.91 70.79,39.64 70.93,39.5 73.64,39.5 73.83,39.31 74.8,39.31 75.5,38.61 75.5,38.25 75.19,37.94 74.47,37.94 74.29,37.76 74.29,37.13 74.46,36.96 74.94,36.96 75.68,36.22 75.92,36.22 76.03,36.33 76.03,37.29 76.35,37.61 v1(77.22,37.61)
DRAM_CS1#: length 34.9
  TOP w0.142: v1(75.65,37.59) 76.11,37.59 76.57,38.05 77.22,38.05 77.46,38.29 77.92,38.29 U7.L1 ; U6.H5 v1(63.81,40.57)
  L3_SIG1 w0.142: v1(75.65,37.59) 75,38.24 73.69,38.24 73.41,38.52 73.41,38.96 73.2,39.17 70.89,39.17 70.41,39.65 69.94,39.65 69.82,39.77 69.82,39.94 69.94,40.06 70.66,40.06 71.08,39.63 72.32,39.63 72.5,39.82 72.5,40.02 71.52,41 71.18,41 70.92,41.26 69.57,41.26 69.45,41.13 69.45,40.79 69.32,40.66 69.15,40.66 69.02,40.79 69.02,41.13 68.89,41.26 68.7,41.26 68.58,41.13 68.58,39.86 68.45,39.73 68.28,39.73 68.15,39.86 68.15,41.07 67.96,41.26 67.78,41.26 67.64,41.12 67.64,39.92 67.52,39.79 67.34,39.79 67.22,39.92 67.22,40.27 67.09,40.39 66.9,40.39 66.77,40.52 66.77,40.69 66.9,40.82 67.09,40.82 67.22,40.94 67.22,41.14 67.66,41.58 67.66,42.12 67.51,42.26 67.31,42.26 67.22,42.17 67.22,41.72 67.08,41.58 66.88,41.58 66.78,41.68 66.78,42.03 66.66,42.16 66.48,42.16 66.36,42.03 66.36,41.38 66.23,41.26 66.08,41.26 65.94,41.4 65.94,42.05 65.81,42.17 65.2,42.17 63.81,40.79 v1(63.81,40.57)
DRAM_DATA0: length 32.7
  TOP w0.142: U7.E3 v1(79.41,43.2) ; U6.T4 v1(63.78,46.97)
  L3_SIG1 w0.142: v1(79.41,43.2) 79.01,43.6 77.57,43.6 77.34,43.83 77.34,44.41 77.44,44.51 78.06,44.51 78.18,44.63 78.18,44.98 78.03,45.12 77.51,45.12 77.34,45.28 77.34,45.5 77.2,45.65 76.86,45.65 76.72,45.79 76.72,46.07 76.86,46.22 77.2,46.22 77.34,46.36 77.34,46.76 77.19,46.91 76.57,46.91 76.43,46.77 76.43,45.74 76.28,45.6 76,45.6 75.86,45.74 75.86,46.77 75.71,46.91 75.43,46.91 75.29,46.77 75.29,46.14 75.15,46 74.86,46 74.72,46.14 74.72,46.77 74.58,46.91 72.13,46.91 71.98,47.06 71.98,47.54 71.84,47.68 71.56,47.68 71.41,47.54 71.41,47.06 71.27,46.91 70.99,46.91 70.85,47.06 70.85,47.56 70.7,47.7 70.42,47.7 70.28,47.56 70.28,47.06 70.13,46.91 69.85,46.91 69.71,47.06 69.71,47.56 69.57,47.7 69.28,47.7 69.14,47.56 69.14,47.06 69,46.91 68.71,46.91 68.57,47.06 68.57,47.56 68.43,47.7 68.14,47.7 68,47.56 68,47.06 67.86,46.91 67.57,46.91 67.43,47.06 67.43,47.56 67.29,47.7 67,47.7 66.86,47.56 66.86,47.06 66.72,46.91 66.24,46.91 65.76,47.4 64.98,47.4 64.55,46.97 v1(63.78,46.97)
DRAM_DATA1: length 32.6
  TOP w0.142: U7.F7 82.57,42.44 82.57,42.45 v1(82.25,42.77) ; U6.U6 62.6,49.2 64.35,50.95 64.94,50.95 65.2,51.22 v1(65.21,51.22)
  L3_SIG1 w0.142: v1(82.25,42.77) 81.93,43.09 81.93,43.78 82.08,43.92 82.94,43.92 83.09,44.06 83.09,44.34 82.94,44.49 82.08,44.49 81.93,44.63 81.93,44.91 82.08,45.06 82.94,45.06 83.09,45.2 83.09,45.48 82.94,45.62 82.08,45.62 81.93,45.77 81.93,46.27 79.97,48.23 79.29,48.23 77.48,50.05 69.93,50.05 69.85,49.97 69.44,49.97 69.06,50.36 67.04,50.36 66.55,50.85 66.55,51.36 66.23,51.69 65.68,51.69 v1(65.21,51.22)
DRAM_DATA2: length 32.6
  TOP w0.142: U6.T6 62.99,47.78 62.99,48.31 63,48.32 v1(63,48.77) ; U7.F2 v1(78.61,42.4)
  L3_SIG1 w0.142: v1(78.61,42.4) 80.09,42.4 80.33,42.64 80.33,44.59 80.19,44.74 79.66,44.74 79.52,44.88 79.52,45.08 79.66,45.22 80.19,45.22 80.33,45.36 80.33,45.57 79.89,46.01 79.67,46.01 78.88,46.79 78.6,46.79 76.73,48.66 68.89,48.66 68.66,48.89 66.49,48.89 65.97,48.37 63.39,48.37 63.02,48 60.75,48 60.55,48.2 60.55,48.56 60.76,48.77 v1(63,48.77)
DRAM_DATA3: length 32.7
  TOP w0.142: v1(68.16,51.18) 67.06,51.18 66.01,52.22 64.4,52.22 61.88,49.71 61.88,48.92 61.8,48.83 61.8,48.72 61.8,48.71 U6.U7 ; U7.F8 v1(84.21,42.4)
  L3_SIG1 w0.142: v1(68.16,51.18) 68.61,51.18 68.82,51.39 69.93,51.39 70.42,50.91 79.2,50.91 80.04,50.07 81.67,50.07 82.23,49.51 82.23,48.23 83.81,46.66 83.81,42.8 v1(84.21,42.4)
DRAM_DATA4: length 32.7
  TOP w0.142: v1(61.03,49.21) 61.03,48.76 61,48.73 U6.U8 ; v1(80.19,40.1) 80.12,40.1 U7.H3
  L3_SIG1 w0.142: v1(80.19,40.1) 80.65,40.1 80.77,40.22 80.77,40.35 80.9,40.48 81.55,40.48 81.68,40.6 81.68,40.78 81.55,40.9 80.78,40.9 80.66,41.03 80.66,41.2 80.78,41.33 81.41,41.33 81.54,41.45 81.54,41.63 81.41,41.76 80.9,41.76 80.77,41.88 80.77,45.74 79.35,47.16 78.72,47.16 76.87,49.01 68.93,49.01 68.71,49.24 66.41,49.24 65.95,48.77 63.88,48.77 63.44,49.21 63.31,49.21 63.06,49.46 62.89,49.46 62.64,49.21 62.46,49.21 62.21,49.46 62.03,49.46 61.78,49.21 v1(61.03,49.21)
DRAM_DATA5: length 32.8
  TOP w0.142: U7.H8 v1(84.21,40.8) ; U6.T8 61.45,47.83 61.45,48.75 61.53,48.83 61.53,49.55 v1(61.2,49.88)
  L3_SIG1 w0.142: v1(61.2,49.88) 63.4,49.88 63.93,49.35 66.04,49.35 66.32,49.63 68.81,49.63 69.15,49.28 70.14,49.28 70.21,49.36 77.01,49.36 78.91,47.46 79.5,47.46 81.15,45.81 81.15,42.51 83.01,40.66 83.01,40.64 83.24,40.41 U7.H8 v1(84.21,40.8)
DRAM_DATA6: length 32.6
  TOP w0.142: U7.G2 v1(78.61,41.6) ; U6.T5 v1(63.81,47.8)
  L3_SIG1 w0.142: v1(78.61,41.6) 78.36,41.6 78.21,41.76 78.21,42.57 78.44,42.8 79.74,42.8 79.9,42.97 79.9,44.28 79.77,44.42 79.5,44.42 79.4,44.31 79.4,43.94 79.33,43.87 79.13,43.87 79.01,43.99 79.01,45.8 77.48,47.33 75.83,47.33 75.69,47.48 75.69,47.7 75.82,47.84 76.56,47.84 76.68,47.95 76.68,48.16 76.52,48.32 75.53,48.32 75.39,48.18 75.39,47.48 75.25,47.33 74.96,47.33 74.82,47.48 74.82,48.18 74.68,48.32 74.39,48.32 74.25,48.18 74.25,47.48 74.11,47.33 73.82,47.33 73.68,47.48 73.68,48.18 73.54,48.32 73.26,48.32 73.11,48.18 73.11,47.48 72.97,47.33 72.56,47.33 72.44,47.45 72.44,48.11 72.25,48.3 68.32,48.3 68.05,48.57 66.73,48.57 65.96,47.8 v1(63.81,47.8)
DRAM_DATA7: length 32.6
  TOP w0.142: U7.H7 v1(83.41,40.8) ; U6.U4 64.2,49.1 64.47,49.38 v1(64.47,49.83)
  L3_SIG1 w0.142: v1(64.47,49.83) 64.02,49.83 63.48,50.37 63.48,50.93 63.73,51.18 64.27,51.18 64.76,50.69 66.1,50.69 66.77,50.01 68.91,50.01 69.3,49.63 70,49.63 70.07,49.71 77.22,49.71 79.04,47.89 79.7,47.89 81.66,45.93 81.66,42.55 82.14,42.07 82.31,42.07 83.01,42.77 83.19,42.77 83.31,42.65 83.31,42.47 82.62,41.77 82.62,41.6 v1(83.41,40.8)
DRAM_DATA8: length 30
  TOP w0.142: v1(83.31,49.49) 82.85,49.49 81.93,48.57 81.93,48.4 81.53,48.01 81.53,44.75 82.37,43.92 82.37,43.75 82.51,43.6 U7.D7 ; U6.U2 66.39,48.78 68.75,48.77 73.03,48.77 74.68,50.42 v1(74.68,51.94)
  BOTTOM w0.142: v1(74.68,51.94) 74.68,50.34 74.97,50.04 78.9,50.04 79.16,50.29 82.59,50.29 82.99,49.89 82.99,49.81 v1(83.31,49.49)
DRAM_DATA9: length 30
  TOP w0.142: v1(71.49,51.87) 70.97,51.87 70.55,51.44 70.55,49.86 70.3,49.62 66.06,49.62 65,48.56 U6.U3 ; v1(80.94,49.2) 79.64,47.91 79.64,47.41 80.77,46.28 80.77,44.96 80.22,44.41 U7.C3
  BOTTOM w0.142: v1(80.94,49.2) 80.54,49.6 79.87,49.6 79.42,49.15 72.26,49.15 71.4,50.02 71.4,50.57 71.54,50.71 72.59,50.71 72.73,50.85 72.73,51.13 72.59,51.28 71.63,51.28 71.49,51.42 v1(71.49,51.87)
DRAM_DATA10: length 29.9
  TOP w0.142: v1(69.63,50.53) 69.17,50.53 69.02,50.69 66.32,50.69 66.2,50.81 66.2,50.85 66.08,50.97 65.9,50.97 65.77,50.85 65.77,50.81 65.65,50.69 65.29,50.69 65.17,50.57 64.48,50.57 63.75,49.85 63.75,48.54 U6.U5 ; v1(82.94,48.76) 82.94,48.31 81.88,47.25 81.88,44.91 82.81,43.98 83.38,43.98 U7.C8
  BOTTOM w0.142: v1(82.94,48.76) 82.02,47.84 72.32,47.84 v1(69.63,50.53)
DRAM_DATA11: length 30
  TOP w0.142: v1(70.49,52.06) 70.17,51.74 70.17,50.35 69.82,50.01 65.96,50.01 64.64,48.69 64.64,47.03 U6.R4 ; U7.C2 79.43,44.83 80.13,44.83 80.39,45.09 80.39,46.09 78.87,47.61 78.87,48.38 79.62,49.13 v1(80.07,49.13)
  BOTTOM w0.142: v1(70.49,52.06) 70.49,50.29 72.47,48.3 79.24,48.3 v1(80.07,49.13)
DRAM_DATA12: length 30
  TOP w0.142: U6.P5 v1(63.81,46.2) ; v1(84.84,49.15) 84.84,48.51 83.01,46.68 U7.A7
  BOTTOM w0.142: v1(63.81,46.2) 64.21,45.8 65.23,45.8 66.93,47.5 68.56,47.5 68.83,47.77 68.83,49.01 69.01,49.18 69.22,49.18 69.4,49.01 69.4,47.64 69.54,47.5 83.19,47.5 v1(84.84,49.15)
DRAM_DATA13: length 30
  TOP w0.142: U7.A2 77.89,47.13 77.89,48.78 81.07,51.96 81.07,52.26 80.85,52.47 80.6,52.47 80.35,52.22 80.18,52.22 79.71,52.68 79.54,52.68 79.41,52.56 79.41,52.38 79.88,51.92 79.88,51.74 79.75,51.62 79.57,51.62 79.1,52.09 78.93,52.09 78.8,51.97 78.8,51.79 79.27,51.32 79.27,51.14 77.41,49.28 76.6,49.28 75.3,47.98 75.3,47.97 74.26,46.93 69.01,46.93 68.31,46.23 65.45,46.23 U6.P3
DRAM_DATA14: length 30.1
  TOP w0.142: U6.R2 66.2,46.99 68.09,46.99 68.73,47.62 73.6,47.62 v1(77.44,51.46) ; U7.B8 83.43,45.58 83.43,46.47 85.68,48.72 85.68,50.83 v1(85.36,51.15)
  BOTTOM w0.142: v1(85.36,51.15) 85.36,51.6 84.39,52.57 78.55,52.57 v1(77.44,51.46)
DRAM_DATA15: length 30
  TOP w0.142: U6.R1 67.26,46.58 67.32,46.64 68.23,46.64 68.87,47.28 73.95,47.28 77.06,50.39 77.23,50.39 77.37,50.25 77.55,50.25 77.67,50.38 77.67,50.55 77.54,50.69 77.54,50.87 v1(78.23,51.56) ; v1(82.68,51.44) 82.68,50.69 82.36,50.38 80.04,50.38 78.45,48.79 78.45,47.37 U7.A3
  BOTTOM w0.142: v1(78.23,51.56) 78.75,52.08 81.05,52.08 81.18,51.95 81.18,51.37 81.3,51.25 81.48,51.25 81.6,51.37 81.6,51.95 81.73,52.08 82.48,52.08 82.68,51.89 v1(82.68,51.44)
DRAM_DQM0: length 32.6
  TOP w0.142: U7.E7 v1(83.41,43.2) ; v1(64.64,51.7) 64.52,51.7 62.25,49.42 62.25,47.83 U6.T7
  L3_SIG1 w0.142: v1(64.64,51.7) 64.98,52.03 65.33,52.03 65.47,52.17 65.47,52.66 65.62,52.8 65.9,52.8 66.04,52.66 66.04,52.17 66.19,52.03 66.59,52.03 67.84,50.78 67.89,50.78 67.96,50.7 69.12,50.7 69.43,51.01 69.82,51.01 70.41,50.43 79,50.43 79.35,50.08 79.35,49.01 79.78,48.58 81.23,48.58 83.41,46.4 v1(83.41,43.2)
DRAM_DQM1: length 30
  TOP w0.142: U7.D3 81.15,44.95 81.15,46.47 80.43,47.2 80.43,47.66 81.67,48.91 v1(81.67,49.36) ; v1(73.57,51.76) 73.49,51.69 72.15,51.69 70.89,50.43 70.89,49.72 70.45,49.28 66.4,49.28 65.45,48.33 65.45,48.18 65.44,48.17 65.44,47.83 U6.T3
  BOTTOM w0.142: v1(73.57,51.76) 73.57,51.35 73.28,51.06 73.28,49.91 73.7,49.49 73.99,49.49 74.12,49.62 74.12,49.91 74.24,50.03 74.42,50.03 74.54,49.91 74.54,49.62 74.67,49.49 79.05,49.49 79.5,49.95 81.08,49.95 v1(81.67,49.36)
DRAM_ODT0: length 34.7
  TOP w0.142: v1(74.17,40.13) 74.17,39.45 74.33,39.29 74.54,39.29 74.65,39.4 74.65,40.71 74.51,40.84 74.13,40.84 74.03,40.95 74.03,41.26 74.17,41.4 76.06,41.4 76.2,41.54 76.2,41.73 76.07,41.86 74.18,41.86 74.06,41.98 74.06,42.22 74.2,42.36 76,42.36 76.2,42.57 76.2,43.31 76.06,43.45 75.82,43.45 75.49,43.12 75.21,43.12 74.88,42.79 74.58,42.79 74.28,43.1 73.97,43.1 73.69,42.82 73.49,42.82 73.29,43.02 73.29,43.52 73.14,43.68 72.64,43.68 72.44,43.87 72.44,44.05 72.49,44.09 72.49,44.27 72.36,44.4 72.19,44.4 72.14,44.35 71.96,44.35 71.84,44.47 71.84,44.65 71.89,44.7 71.89,44.87 71.76,45 71.58,45 71.54,44.95 71.36,44.95 71.15,45.16 70.66,45.16 70.47,44.97 70.23,44.97 70.04,45.16 69.8,45.16 69.61,44.97 69.38,44.97 69.19,45.16 68.95,45.16 68.76,44.97 68.52,44.97 68.33,45.16 68.1,45.16 67.9,44.97 67.67,44.97 67.44,45.2 67.19,45.2 66.97,44.98 U6.N1 ; v1(77.22,38.61) 77.22,39.12 77.34,39.24 77.77,39.24 U7.K1
  BOTTOM w0.142: v1(74.17,40.13) 74.08,40.22 72.43,40.22 72.32,40.33 72.32,40.76 72.46,40.9 73,40.9 73.27,40.63 73.45,40.63 73.7,40.88 74.21,40.88 74.87,40.21 74.88,40.21 76.48,38.61 v1(77.22,38.61)
DRAM_ODT1: length 34.8
  TOP w0.142: v1(74.67,38.74) 74.99,39.06 74.99,40.66 75.25,40.92 76.35,40.92 76.56,41.14 76.56,46.34 76.15,46.75 76.15,47.85 76.35,48.06 76.92,48.06 77.06,47.91 77.06,41.02 76.91,40.86 76.91,39.83 77.13,39.6 U7.J1 ; U6.F1 66.97,39.38 67.13,39.22 68.77,39.22 68.95,39.03 69.55,39.03 v1(69.72,38.86)
  BOTTOM w0.142: v1(74.67,38.74) 74.67,38.64 74.28,38.24 73.69,38.24 73.16,38.78 72.44,38.78 72.35,38.69 70.87,38.69 70.59,38.4 69.78,38.4 69.64,38.26 69.64,38.05 69.76,37.94 70.45,37.94 70.6,37.79 70.6,37.59 70.47,37.47 69.42,37.47 69.29,37.6 69.29,38.66 69.5,38.86 v1(69.72,38.86)
DRAM_RAS#: length 34.7
  TOP w0.142: U7.J3 79.41,40.01 77.58,40.01 77.41,40.18 77.41,48.36 77.27,48.5 76.3,48.5 75.64,47.84 75.64,46.68 76.19,46.13 76.19,44.33 75.33,43.47 73.85,43.47 73.38,43.94 73.38,44.63 73.18,44.83 v1(72.64,44.83) ; U6.M5 v1(63.81,44.6)
  L3_SIG1 w0.142: v1(72.64,44.83) 72.64,44.1 72.43,43.88 71.62,43.88 71.47,44.03 71.47,44.23 71.62,44.38 71.93,44.38 72.03,44.48 72.03,44.69 71.89,44.83 69.5,44.83 68.99,45.34 66.26,45.34 65.76,45.85 65.3,45.85 65.01,45.56 65.01,45.2 64.81,45 64.21,45 v1(63.81,44.6)
DRAM_RESET#: length 34.9
  TOP w0.142: U7.T2 v1(78.61,33.61) ; U6.G4 v1(64.61,39.77)
  L3_SIG1 w0.142: v1(64.61,39.77) 65.01,39.37 65.01,37.21 65.25,36.97 65.76,36.97 66.24,36.49 66.24,36.32 65.82,35.9 65.82,35.72 65.95,35.6 66.12,35.6 66.54,36.01 66.72,36.01 66.98,35.75 67.16,35.75 67.46,36.06 67.64,36.06 67.76,35.93 67.76,35.75 67.46,35.45 67.46,35.27 67.58,35.15 67.76,35.15 68.06,35.45 68.24,35.45 68.37,35.33 68.37,35.15 68.06,34.85 68.06,34.67 68.19,34.54 68.36,34.54 68.67,34.85 68.84,34.85 68.97,34.72 68.97,34.55 68.67,34.24 68.67,34.06 68.79,33.94 68.97,33.94 69.27,34.24 69.45,34.24 69.57,34.12 69.57,33.94 69.27,33.64 69.27,33.46 70.46,32.27 71.38,32.27 71.86,32.75 72.22,32.75 72.34,32.63 72.34,31.87 72.47,31.75 72.65,31.75 72.77,31.87 72.77,32.63 72.9,32.75 73.95,32.75 75.01,31.69 75.52,31.69 75.64,31.82 75.64,32.32 75.77,32.44 75.94,32.44 76.07,32.32 76.07,31.82 76.19,31.69 76.37,31.69 76.5,31.82 76.5,32.32 76.62,32.44 76.8,32.44 76.92,32.32 76.92,31.82 77.05,31.69 77.22,31.69 77.35,31.82 77.35,32.32 77.47,32.44 77.65,32.44 77.78,32.32 77.78,31.82 77.9,31.69 78.31,31.69 78.61,31.99 v1(78.61,33.61)
  BOTTOM w0.142: R64.2 79.15,34.14 v1(78.61,33.61)
DRAM_SDBA0: length 34.7
  TOP w0.142: U6.M1 66.98,44.18 67.08,44.28 71.06,44.28 73.32,42.02 73.32,38.64 73.41,38.55 73.41,38.52 73.8,38.13 v1(73.8,37.65) ; U7.M2 v1(78.61,36.81)
  L3_SIG1 w0.142: v1(78.61,36.81) 78.21,36.41 77.05,36.41 76.93,36.53 76.93,36.65 76.8,36.77 76.62,36.77 76.5,36.65 76.5,36.53 76.37,36.41 76.08,36.41 75.94,36.55 75.94,36.92 75.81,37.04 75.64,37.04 75.51,36.92 75.51,36.72 75.37,36.57 75.17,36.57 74.86,36.88 74.86,37.76 74.73,37.89 74.56,37.89 74.43,37.76 74.43,36.83 74.28,36.68 72.57,36.68 72.3,36.95 69.17,36.95 68.72,37.4 68.72,37.81 68.87,37.95 69.15,37.95 69.28,37.83 69.28,37.48 69.4,37.35 69.58,37.35 69.71,37.48 69.71,37.83 69.83,37.95 70.03,37.95 70.14,37.83 70.14,37.51 70.28,37.37 70.49,37.37 70.63,37.51 70.63,37.81 70.78,37.95 70.98,37.95 71.12,37.81 71.12,37.54 71.33,37.33 72.53,37.33 72.76,37.1 73.58,37.1 73.8,37.32 v1(73.8,37.65)
DRAM_SDBA1: length 35.1
  TOP w0.142: U7.N8 83.43,36.03 82.44,36.03 82.29,35.89 82.29,35.65 82.2,35.56 81.94,35.56 81.8,35.7 81.8,36.12 81.92,36.25 82.11,36.25 82.23,36.37 82.23,36.55 82.11,36.67 81.92,36.67 81.8,36.8 81.8,37.96 81.46,38.29 81.12,38.29 80.84,38.02 80.84,37.79 80.97,37.66 81.32,37.66 81.44,37.54 81.44,37.36 81.32,37.24 80.97,37.24 80.84,37.11 80.84,36.93 80.97,36.81 81.32,36.81 81.44,36.68 81.44,36.51 81.32,36.38 81.05,36.38 80.93,36.26 80.93,35.9 81.05,35.78 81.25,35.78 81.37,35.65 81.37,35.48 81.25,35.35 81.05,35.35 80.93,35.23 80.93,35.05 81.05,34.93 81.16,34.93 81.29,34.8 81.29,34.62 81.16,34.5 81.11,34.5 80.98,34.37 80.98,33.61 80.14,32.77 77.32,32.77 76.93,33.15 76.93,35.68 76.09,36.53 75.82,36.53 75.63,36.72 75.4,36.72 75.2,36.52 74.97,36.52 74.77,36.72 74.54,36.72 74.35,36.52 73.01,36.52 72.16,37.37 71.43,37.37 71.15,37.65 71.15,39.22 69.95,40.42 69.95,40.78 69.7,41.04 69.25,41.04 68.83,40.61 67.61,40.61 67.24,40.98 U6.H1
DRAM_SDBA2: length 34.7
  TOP w0.142: U7.M3 v1(79.41,36.81) ; U6.K2 66.22,42.16 67.52,42.16 67.75,42.39 68.6,42.39 68.76,42.22 v1(69.22,42.22)
  BOTTOM w0.142: v1(79.41,36.81) 81.45,36.81 81.59,36.66 81.59,36.39 81.74,36.24 82.11,36.24 82.26,36.38 82.26,37.39 81.81,37.84 81.47,37.84 81.34,37.71 81.34,37.26 81.22,37.14 81.04,37.14 80.91,37.26 80.91,37.71 80.79,37.84 80.23,37.84 79.62,37.23 79.6,37.23 79.57,37.21 79.17,37.21 79.17,37.2 76.65,37.2 76.39,36.95 76.39,35.98 76.22,35.81 75.55,35.81 74.75,36.61 74.19,36.61 73.98,36.82 73.68,36.82 73.47,36.61 73.27,36.61 73.12,36.75 73.12,36.97 72.98,37.11 72.74,37.11 72.62,37 72.62,36.72 72.51,36.61 72.27,36.61 72.13,36.75 72.13,38.05 71.83,38.34 71.19,38.34 71.01,38.17 71.01,37.72 71.28,37.45 71.28,36.55 71.18,36.44 70.94,36.44 70.33,37.05 69.39,37.05 68.99,37.45 68.99,41.55 69.22,41.77 v1(69.22,42.22)
DRAM_SDCKE0: length 34.8
  TOP w0.142: U6.M3 v1(65.41,44.6) ; U7.K9 v1(86.64,38.81) 87.3,38.81 R60.1
  L3_SIG1 w0.142: v1(65.41,44.6) 68.76,44.6 69.32,44.03 69.71,44.03 69.71,44.03 70.44,44.03 71.48,43 72.09,43 73.52,41.56 74.21,41.56 76.42,39.35 77.53,39.35 78.08,38.8 78.89,38.8 79.4,39.31 81.19,39.31 82.65,37.85 84.69,37.85 85.27,38.43 85.27,39.84 86.9,41.47 87.35,41.47 87.5,41.33 87.5,40.92 87.35,40.78 86.85,40.78 86.64,40.57 v1(86.64,38.81)
DRAM_SDCKE1: length 35.3
  TOP w0.142: U6.J3 v1(65.41,41.37) ; U7.J9 84.98,39.98 v1(87.12,39.98) 87.33,39.98 R58.1
  L3_SIG1 w0.142: v1(65.41,41.37) 66.44,40.34 66.44,37.66 67.23,36.88 67.62,36.88 68.45,36.05 69.22,36.05 69.54,35.72 71.9,35.72 72.22,35.4 72.22,34.94 72.45,34.71 76.42,34.71 77.12,34.01 77.97,34.01 78.21,34.24 78.21,34.57 78.44,34.8 80.62,34.8 81.42,35.6 82.87,35.6 82.88,35.61 86.11,35.61 87.12,36.61 v1(87.12,39.98)
DRAM_SDCLK0_N: length 35.2
  TOP w0.102: v1(74.03,44.14) 74.23,44.34 74.23,44.78 74.48,45.03 75.36,45.03 75.46,45.13 75.46,45.45 75.36,45.55 73.73,45.55 73.5,45.79 73.5,46.11 73.41,46.2 73.28,46.2 73.19,46.11 73.19,45.79 72.95,45.55 69.76,45.55 69.52,45.79 69.52,46.1 69.43,46.19 69.3,46.19 69.22,46.1 69.22,45.79 68.98,45.55 66.84,45.55 66.73,45.45 66.46,45.45 66.13,45.78 U6.P2 ; v1(82.25,38.82) 82.51,39.08 82.73,39.08 U7.K7
  BOTTOM w0.102: v1(82.25,38.82) 82.14,38.93 81.5,38.93 R67.1 81.21,38.72 80.94,38.99 79.97,38.99 79.91,39.05 79.9,39.05 79.41,39.54 79.21,39.54 79.09,39.65 79.09,39.86 78.95,40.01 76.86,40.01 75.38,41.48 75.38,44.82 75.29,44.91 75.1,44.91 75.02,45 75.02,45.12 75.1,45.21 75.29,45.21 75.38,45.3 75.38,45.55 74.78,46.16 73.62,46.16 73.47,46.01 73.47,45.76 73.56,45.68 74.19,45.68 74.42,45.44 74.42,45.1 74.19,44.86 73.57,44.86 73.47,44.76 73.47,43.77 73.57,43.67 74.13,43.67 74.23,43.77 74.23,43.94 v1(74.03,44.14)
DRAM_SDCLK0_P: length 35.3
  TOP w0.102: v1(74.69,44.14) 74.49,44.35 74.49,44.68 74.59,44.78 75.46,44.78 75.71,45.03 75.71,45.56 75.46,45.81 73.84,45.81 73.75,45.9 73.75,46.22 73.51,46.46 73.17,46.46 72.94,46.22 72.94,45.9 72.85,45.81 69.86,45.81 69.77,45.9 69.77,46.2 69.54,46.44 69.2,46.44 68.96,46.2 68.96,45.9 68.87,45.81 66.62,45.81 U6.P1 ; U7.J7 82.73,39.33 82.4,39.33 v1(82.25,39.48)
  BOTTOM w0.102: v1(82.25,39.48) 82.08,39.3 81.49,39.3 R67.2 81.21,39.52 80.94,39.24 80.08,39.24 80.02,39.31 80.01,39.31 79.06,40.26 76.96,40.26 75.64,41.59 75.64,45.66 74.88,46.41 73.51,46.41 73.21,46.11 73.21,45.66 73.45,45.42 74.08,45.42 74.17,45.33 74.17,45.21 74.08,45.12 73.46,45.12 73.21,44.87 73.21,43.67 73.46,43.42 74.24,43.42 74.49,43.67 74.49,43.93 v1(74.69,44.14)
DRAM_SDQS0_N: length 32.8
  TOP w0.102: U7.G3 v1(80.21,40.81) ; U6.P7 v1(61.38,45.37)
  L3_SIG1 w0.102: v1(61.38,45.37) 61.81,45.8 64.85,45.8 65.15,46.1 66.28,46.1 66.6,45.78 69.39,45.78 69.86,45.31 73.15,45.31 73.4,45.56 73.4,46.08 73.5,46.18 73.7,46.18 73.8,46.08 73.8,45.57 74.09,45.29 75.37,45.29 75.38,45.28 75.39,45.28 76.49,44.18 76.49,43.75 76.35,43.6 74.73,43.6 74.48,43.35 74.48,42.86 74.73,42.61 76.81,42.61 77.02,42.4 77.02,42.03 76.92,41.93 76.02,41.93 75.77,41.68 75.77,41.26 76.02,41.01 76.92,41.01 77.02,40.91 77.02,40.38 77.27,40.13 79.44,40.13 79.69,40.38 79.69,40.98 79.79,41.08 79.93,41.08 v1(80.21,40.81)
DRAM_SDQS0_P: length 32.7
  TOP w0.102: U7.F3 v1(80.21,41.61) ; U6.P6 v1(63.01,46.2)
  L3_SIG1 w0.102: v1(63.01,46.2) 63.4,46.58 64.92,46.58 65.16,46.35 66.39,46.35 66.7,46.03 66.86,46.03 66.95,46.12 66.95,46.25 67.04,46.34 67.16,46.34 67.25,46.25 67.25,46.12 67.34,46.03 67.47,46.03 67.56,46.12 67.56,46.25 67.64,46.34 67.77,46.34 67.86,46.25 67.86,46.12 67.95,46.03 68.08,46.03 68.17,46.12 68.17,46.25 68.25,46.34 68.38,46.34 68.47,46.25 68.47,46.12 68.56,46.03 68.69,46.03 68.77,46.12 68.77,46.25 68.86,46.34 68.99,46.34 69.08,46.25 69.08,46.12 69.17,46.03 69.5,46.03 69.96,45.57 73.04,45.57 73.14,45.67 73.14,46.19 73.39,46.44 73.81,46.44 74.06,46.19 74.06,45.68 74.19,45.54 75.48,45.54 75.49,45.53 75.5,45.53 76.75,44.28 76.75,43.64 76.46,43.35 74.83,43.35 74.73,43.25 74.73,42.96 74.83,42.86 76.92,42.86 77.27,42.5 77.27,41.92 77.02,41.67 76.12,41.67 76.02,41.57 76.02,41.37 76.12,41.27 77.02,41.27 77.27,41.02 77.27,40.49 77.37,40.39 79.33,40.39 79.43,40.49 79.43,41.08 79.68,41.33 79.93,41.33 v1(80.21,41.61)
DRAM_SDQS1_N: length 30
  TOP w0.102: U6.T2 66.13,47.71 68,47.71 68.67,48.39 73.27,48.39 76.07,51.19 76.07,51.4 75.87,51.6 v1(75.87,51.82) ; U7.B7 82.65,45.2 82.55,45.31 82.55,47.01 84.2,48.66 84.2,50.8 84.4,51 v1(84.4,51.44)
  BOTTOM w0.102: v1(75.87,51.82) 76.07,51.61 76.07,50.84 76.34,50.57 78.57,50.57 78.67,50.67 83.95,50.67 84.2,50.92 84.2,51.23 v1(84.4,51.44)
